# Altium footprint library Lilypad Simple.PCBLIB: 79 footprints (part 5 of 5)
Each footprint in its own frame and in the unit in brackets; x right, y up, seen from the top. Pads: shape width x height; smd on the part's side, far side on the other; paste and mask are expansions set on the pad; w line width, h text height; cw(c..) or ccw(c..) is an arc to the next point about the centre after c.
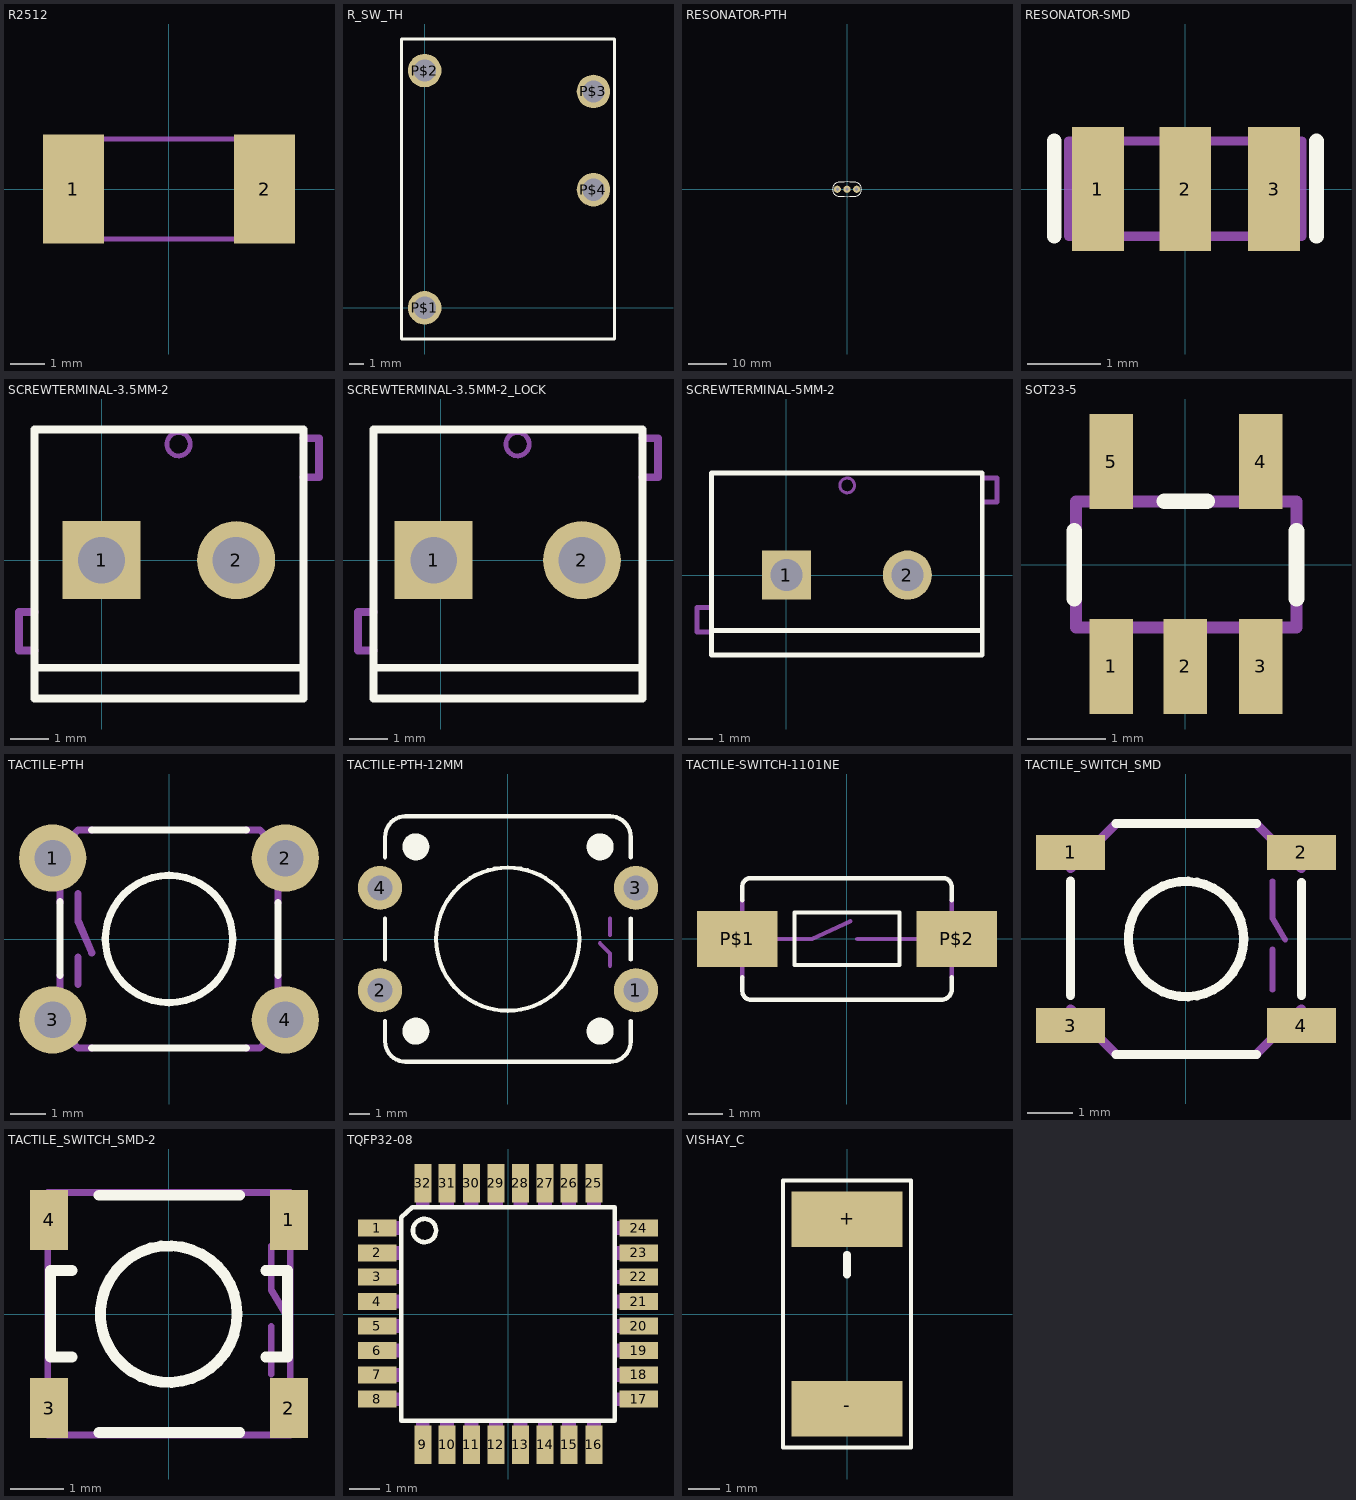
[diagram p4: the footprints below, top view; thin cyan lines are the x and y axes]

## R2512 [mil]
pads (2):
  rect 71x126 smd: 1(-110.24,0) 2(111,0)
Courtyard Bottom:
  rectangle: -126,-61 -92.54,62
  rectangle: 93,-61 127,62
  lines w6: -92.99,-57.99 94,-57.99 ; -92.99,58 94,58

## R_SW_TH [mil]
pads (4):
  round 94.5 hole 63: P$1(0,0) P$2(0,669) P$3(476,610) P$4(476,333)
Top Overlay:
  lines w8: -65,-88 -65,758 535,758 535,-88 -65,-88

## RESONATOR-PTH [mil]
pads (3):
  round 74 hole 32: 1(-100,0) 2(0,0) 3(100,0)
Top Overlay:
  lines w8: -90,-70 cw(c-79.17,0) -90,70 cw(c0,-735) 90,70 cw(c79.17,0) 90,-70 cw(c0,737.5) -90,-70

## RESONATOR-SMD [mil]
pads (3):
  rect 28x67 smd: 1(-47.24,0) 2(0,0) 3(48,0)
Top Overlay:
  lines w8: -70.87,-25.59 -70.87,26 ; 71,-25.59 71,26
Courtyard Bottom:
  lines w5: -62.99,-25.59 63,-25.59 63,26 -62.99,26 -62.99,-25.59

## SCREWTERMINAL-3.5MM-2 [mil]
pads (2):
  rect 80x80 hole 48: 1(0,0)
  round 80 hole 48: 2(138,0)
Top Overlay:
  lines w8: -68.9,-110.24 -68.9,-141.73 207,-141.73 207,-110.24 ; -68.9,-110.24 -68.9,134 207,134 207,-110.24 ; -68.9,-110.24 207,-110.24
Courtyard Bottom:
  circle w5: c79,119 r12
  lines w8: -68.9,-92.52 -84.65,-92.52 -84.65,-53.15 -68.9,-53.15 ; 207,85 223,85 223,125 207,125

## SCREWTERMINAL-3.5MM-2_LOCK [mil]
pads (2):
  rect 80x80 hole 48: 1(-7,0)
  round 80 hole 48: 2(145,0)
Top Overlay:
  lines w8: -68.9,-110.24 -68.9,-141.73 207,-141.73 207,-110.24 ; -68.9,-110.24 -68.9,134 207,134 207,-110.24 ; -68.9,-110.24 207,-110.24
Courtyard Bottom:
  circle w5: c79,119 r12
  circle w1: c0,0 r17
  circle w1: c138,0 r17
  lines w8: -68.9,-92.52 -84.65,-92.52 -84.65,-53.15 -68.9,-53.15 ; 207,85 223,85 223,125 207,125

## SCREWTERMINAL-5MM-2 [mil]
pads (2):
  rect 80x80 hole 52: 1(0,0)
  round 80 hole 52: 2(197,0)
Top Overlay:
  lines w8: -122.05,-90.55 -122.05,-129.92 319,-129.92 319,-90.55 ; -122.05,-90.55 -122.05,166 319,166 319,-90.55 ; -122.05,-90.55 319,-90.55
Courtyard Bottom:
  circle w5: c99,146 r12
  lines w8: -122.05,-92.52 -145.67,-92.52 -145.67,-53.15 -122.05,-53.15 ; 319,119 343,119 343,158 319,158

## SOT23-5 [mil]
pads (5):
  rect 22x48 smd: 1(-37.4,-51.19) 2(0,-51.19) 3(38,-51.19) 4(38,52) 5(-37.4,52)
Top Overlay:
  lines w8: -56,-16.91 -56,17 ; -10.57,32 11,32 ; 56,-16.91 56,17
Courtyard Bottom:
  rectangle: -47.24,-59.06 -27.56,-33.46
  rectangle: -9.84,-59.06 10,-33.46
  rectangle: 28,-59.06 48,-33.46
  rectangle: 28,34 48,60
  rectangle: -47.24,34 -27.56,60
  lines w6: -55.12,-31.5 56,-31.5 56,32 -55.12,32 -55.12,-31.5

## TACTILE-PTH [mil]
pads (4):
  round 74 hole 40: 1(-128,89) 2(128,89) 3(-128,-89) 4(128,-89)
Top Overlay:
  circle w8: c0,0 r70
  lines w8: -120,-40 -120,41 ; -85,-120 85,-120 ; -85,120 85,120 ; 120,-40 120,40
Courtyard Bottom:
  lines w8: -120,-40 -120,-100 -100,-120 -85,-120 ; -120,40 -120,100 -100,120 -85,120 ; -100,-50 -100,-20 ; -100,50 -100,20 -85,-15 ; 85,-120 100,-120 120,-100 120,-40 ; 85,120 100,120 120,100 120,40

## TACTILE-PTH-12MM [mil]
pads (4):
  round 85 hole 48: 1(247,-98.43) 2(-246.06,-98.43) 3(247,99) 4(-246.06,99)
Top Overlay:
  circle w8: c0,0 r138
  circle w28: c-177.17,178 r12
  circle w28: c178,178 r12
  circle w28: c178,-177.17 r12
  circle w28: c-177.17,-177.17 r12
  lines w8: -236.22,-157.48 -236.22,-196.85 ccw(c-196.85,-196.85) -196.85,-236.22 197,-236.22 ccw(c197.31,-196.54) 237,-196.85 237,-157.48 ; -236.22,-39.37 -236.22,40 ; -236.22,158 -236.22,197 cw(c-196.54,197.31) -196.85,237 197,237 cw(c197,197) 237,197 237,158 ; 237,-39.37 237,40
Courtyard Bottom:
  lines w8: 178,-7.87 197,-27.56 197,-51.18 ; 197,8 197,40

## TACTILE-SWITCH-1101NE [mil]
pads (2):
  rect 91x63 smd: P$1(-124.02,0) P$2(125,0)
Top Overlay:
  lines w5: -118.11,-43.31 -118.11,-59.06 ccw(c-108.27,-59.06) -108.27,-68.9 105,-68.9 ccw(c107.08,-56.98) 119,-59.06 119,-43.31 ; -118.11,44 -118.11,60 cw(c-108.69,59.58) -108.27,69 109,69 cw(c109.5,59.5) 119,60 119,44 ; -59.06,-29.53 60,-29.53 60,30 -59.06,30 -59.06,-29.53
Courtyard Bottom:
  lines w5: -118.11,-43.31 -118.11,44 ; -78.74,0 -39.37,0 4,20 ; 12,0 79,0 ; 119,-43.31 119,44

## TACTILE_SWITCH_SMD [mil]
pads (4):
  rect 60x30 smd: 1(-100,75) 2(100,75) 3(-100,-75) 4(100,-75)
Top Overlay:
  circle w8: c0,0 r50
  lines w8: -100,-48.82 -100,50 ; -60.63,-100 61,-100 ; -60.63,100 61,100 ; 100,-48.82 100,49
Courtyard Bottom:
  lines w5: 75,-43.9 75,-9.06 ; 75,50 75,18 86,-0.39
  lines w8: -100,-60.63 -60.63,-100 ; -100,61 -60.63,100 ; 61,-100 100,-60.63 ; 61,100 100,61

## TACTILE_SWITCH_SMD-2 [mil]
pads (4):
  rect 28x44 smd: 1(88,69) 2(88,-68.9) 3(-87.6,-68.9) 4(-87.6,69)
Top Overlay:
  circle w8: c0,0 r50
  lines w8: -70.87,-31.5 -86.61,-31.5 -86.61,32 -70.87,32 ; -51.18,-86.61 52,-86.61 ; -51.18,87 52,87 ; 71,-31.5 87,-31.5 87,32 71,32
Courtyard Bottom:
  lines w5: 75,-43.9 75,-9.06 ; 75,50 75,18 86,-0.39 ; -88.58,-88.58 89,-88.58 89,89 -88.58,89 -88.58,-88.58

## TQFP32-08 [mil]
pads (32):
  rect 50x22 smd: 1(-169,111) 2(-169,79) 3(-169,48) 4(-169,16) 5(-169,-15.75) 6(-169,-47.24) 7(-169,-78.74) 8(-169,-110.24) 17(169,-110.24) 18(169,-78.74) 19(169,-47.24) 20(169,-15.75) 21(169,16) 22(169,48) 23(169,79) 24(169,111)
  rect 22x50 smd: 9(-110.24,-169) 10(-78.74,-169) 11(-47.24,-169) 12(-15.75,-169) 13(16,-169) 14(48,-169) 15(79,-169) 16(111,-169) 25(111,169) 26(79,169) 27(48,169) 28(16,169) 29(-15.75,169) 30(-47.24,169) 31(-78.74,169) 32(-110.24,169)
Top Overlay:
  circle w6: c-108,108 r15
  lines w6: -137.99,-137.99 138,-137.99 138,138 -124.02,138 -137.99,125 -137.99,-137.99
Courtyard Bottom:
  rectangle: -179,102 -140,120
  rectangle: -179,70 -140,88
  rectangle: -179,39 -140,57
  rectangle: -179,7 -140,25
  rectangle: -179,-24.75 -140,-6.75
  rectangle: -179,-56.24 -140,-38.24
  rectangle: -179,-87.74 -140,-69.74
  rectangle: -179,-119.24 -140,-101.24
  rectangle: -119.24,-179 -101.24,-140
  rectangle: -87.74,-179 -69.74,-140
  rectangle: -56.24,-179 -38.24,-140
  rectangle: -24.75,-179 -6.75,-140
  rectangle: 7,-179 25,-140
  rectangle: 39,-179 57,-140
  rectangle: 70,-179 88,-140
  rectangle: 102,-179 120,-140
  rectangle: 140,-119.24 179,-101.24
  rectangle: 140,-87.74 179,-69.74
  rectangle: 140,-56.24 179,-38.24
  rectangle: 140,-24.75 179,-6.75
  rectangle: 140,7 179,25
  rectangle: 140,39 179,57
  rectangle: 140,70 179,88
  rectangle: 140,102 179,120
  rectangle: 102,140 120,179
  rectangle: 70,140 88,179
  rectangle: 39,140 57,179
  rectangle: 7,140 25,179
  rectangle: -24.75,140 -6.75,179
  rectangle: -56.24,140 -38.24,179
  rectangle: -87.74,140 -69.74,179
  rectangle: -119.24,140 -101.24,179

## VISHAY_C [mil]
pads (2):
  rect 140x70 smd: +(0,120) -(0,-120)
Top Overlay:
  lines w5: -81,-169 81,-169 81,169 -81,169 -81,-169
  lines w10: 0,50 0,75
